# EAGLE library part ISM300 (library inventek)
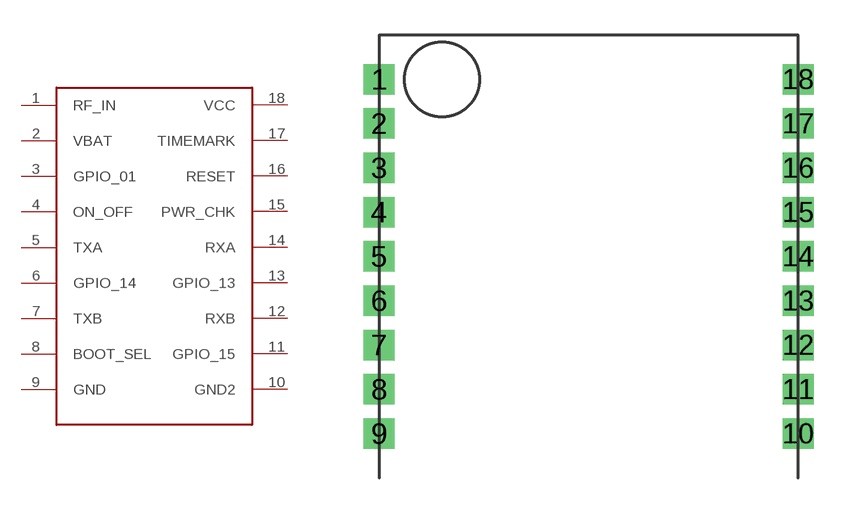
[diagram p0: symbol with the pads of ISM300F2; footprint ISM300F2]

Designator prefix -

## ISM300  [ISM300F2]
1  RF_IN
2  VBAT
3  GPIO_01
4  ON_OFF
5  TXA
6  GPIO_14
7  TXB
8  BOOT_SEL
9  GND
10  GND2
11  GPIO_15
12  RXB
13  GPIO_13
14  RXA
15  PWR_CHK
16  RESET
17  TIMEMARK
18  VCC

## Footprint ISM300F2 (pad centres in mm)
drill 0.8 square: 1 -15.2,9.5; 2 -15.2,7.6; 3 -15.2,5.7; 4 -15.2,3.8; 5 -15.2,1.9; 6 -15.2,0; 7 -15.2,-1.9; 8 -15.2,-3.8; 9 -15.2,-5.7; 10 2.78,-5.7; 11 2.78,-3.8; 12 2.78,-1.9; 13 2.78,0; 14 2.78,1.9; 15 2.78,3.8; 16 2.78,5.7; 17 2.78,7.6; 18 2.78,9.5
